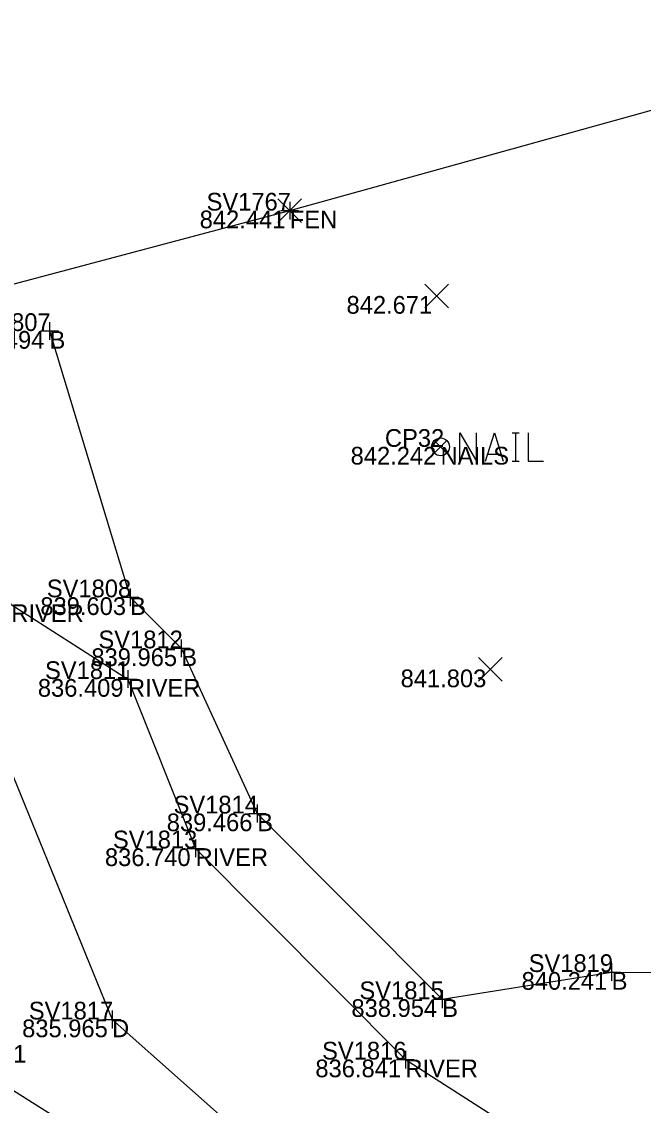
# Model space of a CAD drawing. Extents: x 2125299 to 2129212, y 713100 to 714300.
# Drawn here: x 2127768.7 to 2127803.8, y 713609 to 713670.1 of the extents above; entities that cross this region are included whole.
import ezdxf

# ---------------------------------------------------------------- set-up
doc = ezdxf.new("R2010")
doc.units = 0
for name, color, linetype in [('DR_X_Ditch', 7, 'Continuous'), ('HY_X_Water_Edge', 7, 'Continuous'), ('RD_X_Fence', 7, 'Continuous'), ('RW_P_Esmt_TMP', 7, 'Continuous'), ('RW_X_Esmt_CH', 7, 'Continuous'), ('RW_X_Fee_WL', 7, 'Continuous'), ('SV_X_Break_Lines', 7, 'Continuous'), ('SV_X_Mon_Cells_Found', 7, 'Continuous'), ('SV_X_Text_Elevation', 7, 'Continuous'), ('SV_X_Text_Name', 7, 'Continuous')]:
    doc.layers.add(name, color=color, linetype=linetype)

msp = doc.modelspace()

# ---------------------------------------------------------------- linework, layer by layer
at = {"layer": 'DR_X_Ditch'}
msp.add_lwpolyline([(2127754.532, 713650.693), (2127755.508, 713649.81), (2127761.022, 713641.797), (2127767.377, 713629.627), (2127773.825, 713613.836), (2127787.097, 713602.059), (2127796.409, 713596.425), (2127812.41, 713592.759), (2127822.136, 713591.387), (2127830.865, 713593.325), (2127835.513, 713593.154), (2127840.963, 713588.862), (2127844.441, 713576.862)], dxfattribs=at)
at = {"layer": 'HY_X_Water_Edge'}
for points in [[(2127760.756, 713650.39), (2127768.145, 713637.253), (2127774.726, 713633.041), (2127778.539, 713623.49), (2127790.379, 713611.577), (2127799.446, 713605.767), (2127811.759, 713595.2), (2127821.632, 713592.889), (2127831.559, 713597.952), (2127834.894, 713597.211), (2127837.24, 713606.78), (2127846.533, 713615.952), (2127858.456, 713615.157), (2127864.185, 713615.01), (2127868.763, 713619.475), (2127877.26, 713624.249)], [(2127759.038, 713637.436), (2127761.132, 713628.448), (2127763.153, 713621.237), (2127764.162, 713612.401), (2127775.864, 713605.035), (2127792.881, 713593.368), (2127809.847, 713589.645), (2127822.201, 713590.682), (2127831.261, 713591.73)]]:
    msp.add_lwpolyline(points, dxfattribs=at)
at = {"layer": 'RD_X_Fence'}
msp.add_lwpolyline([(2127758.111, 713652.62), (2127783.853, 713659.466), (2127880.444, 713686.281), (2127925.778, 713698.517)], dxfattribs=at)
at = {"layer": 'SV_X_Break_Lines'}
msp.add_lwpolyline([(2127770.299, 713652.673), (2127774.846, 713637.652), (2127777.731, 713634.773), (2127782.017, 713625.457), (2127792.452, 713614.981), (2127802.011, 713616.513), (2127817.349, 713616.435)], dxfattribs=at)
at = {"layer": 'SV_X_Mon_Cells_Found'}
for p, q in [((2127783.853, 713659.966), (2127783.853, 713658.966)), ((2127783.353, 713659.466), (2127784.353, 713659.466)), ((2127783.853, 713659.466), (2127783.853, 713659.466)), ((2127770.299, 713653.173), (2127770.299, 713652.173)), ((2127769.799, 713652.673), (2127770.799, 713652.673)), ((2127770.299, 713652.673), (2127770.299, 713652.673)), ((2127774.846, 713638.152), (2127774.846, 713637.152)), ((2127774.346, 713637.652), (2127775.346, 713637.652)), ((2127774.846, 713637.652), (2127774.846, 713637.652)), ((2127777.731, 713635.273), (2127777.731, 713634.273)), ((2127777.231, 713634.773), (2127778.231, 713634.773)), ((2127777.731, 713634.773), (2127777.731, 713634.773)), ((2127774.726, 713633.541), (2127774.726, 713632.541)), ((2127774.226, 713633.041), (2127775.226, 713633.041)), ((2127774.726, 713633.041), (2127774.726, 713633.041)), ((2127782.017, 713625.957), (2127782.017, 713624.957)), ((2127781.517, 713625.457), (2127782.517, 713625.457)), ((2127782.017, 713625.457), (2127782.017, 713625.457)), ((2127778.039, 713623.49), (2127779.039, 713623.49)), ((2127778.539, 713623.99), (2127778.539, 713622.99)), ((2127778.539, 713623.49), (2127778.539, 713623.49)), ((2127802.011, 713617.013), (2127802.011, 713616.013)), ((2127801.511, 713616.513), (2127802.511, 713616.513)), ((2127802.011, 713616.513), (2127802.011, 713616.513)), ((2127791.952, 713614.981), (2127792.952, 713614.981)), ((2127792.452, 713615.481), (2127792.452, 713614.481)), ((2127792.452, 713614.981), (2127792.452, 713614.981)), ((2127773.825, 713614.336), (2127773.825, 713613.336)), ((2127773.325, 713613.836), (2127774.325, 713613.836)), ((2127773.825, 713613.836), (2127773.825, 713613.836)), ((2127790.379, 713612.077), (2127790.379, 713611.077)), ((2127789.879, 713611.577), (2127790.879, 713611.577)), ((2127790.379, 713611.577), (2127790.379, 713611.577))]:
    msp.add_line(p, q, dxfattribs=at)
at = {"layer": 'SV_X_Text_Elevation'}
for p, q in [((2127783.186, 713658.798), (2127784.52, 713660.133)), ((2127783.186, 713660.133), (2127784.52, 713658.798)), ((2127791.468, 713653.979), (2127792.802, 713655.314)), ((2127791.468, 713655.314), (2127792.802, 713653.979)), ((2127794.503, 713632.911), (2127795.837, 713634.246)), ((2127794.503, 713634.246), (2127795.837, 713632.911))]:
    msp.add_line(p, q, dxfattribs=at)
at = {"layer": 'SV_X_Text_Name'}
for p, q in [((2127792.005, 713646.492), (2127792.713, 713645.785)), ((2127792.005, 713645.785), (2127792.713, 713646.492))]:
    msp.add_line(p, q, dxfattribs=at)
for points in [[(2127793.449, 713645.329), (2127793.449, 713646.929), (2127794.393, 713645.329), (2127794.393, 713646.929)], [(2127794.897, 713645.329), (2127795.401, 713646.929), (2127795.892, 713645.329)], [(2127796.396, 713646.929), (2127796.799, 713646.929)], [(2127796.598, 713645.329), (2127796.598, 713646.929)], [(2127797.303, 713646.929), (2127797.303, 713645.329), (2127798.173, 713645.329)], [(2127795.766, 713645.706), (2127795.023, 713645.706)], [(2127796.396, 713645.329), (2127796.799, 713645.329)]]:
    msp.add_lwpolyline(points, dxfattribs=at)
msp.add_circle((2127792.359, 713646.138), 0.5, dxfattribs=at)

# ---------------------------------------------------------------- texts
at = {"layer": 'RW_P_Esmt_TMP'}
for s, p in [('FEN', (2127783.853, 713658.466)), ('B', (2127770.299, 713651.673)), ('NAILS', (2127792.359, 713645.138)), ('B', (2127774.846, 713636.652)), ('RIVER', (2127768.145, 713636.253)), ('B', (2127777.731, 713633.773)), ('RIVER', (2127774.726, 713632.042)), ('B', (2127782.017, 713624.457)), ('RIVER', (2127778.539, 713622.49)), ('B', (2127802.011, 713615.513)), ('B', (2127792.452, 713613.981)), ('D', (2127773.825, 713612.836)), ('RIVER1', (2127764.162, 713611.401)), ('RIVER', (2127790.379, 713610.577))]:
    msp.add_text(s, height=1, dxfattribs=at).set_placement(p)
at = {"layer": 'RW_X_Esmt_CH'}
for s, p in [('SV1767', (2127779.159, 713659.466)), ('SV1807', (2127765.605, 713652.673)), ('CP32', (2127789.22, 713646.138)), ('SV1808', (2127770.147, 713637.652)), ('SV1812', (2127773.06, 713634.773)), ('SV1811', (2127770.046, 713633.041)), ('SV1814', (2127777.297, 713625.457)), ('SV1813', (2127773.877, 713623.49)), ('SV1819', (2127797.329, 713616.513)), ('SV1815', (2127787.783, 713614.981)), ('SV1817', (2127769.131, 713613.836)), ('SV1816', (2127785.677, 713611.577))]:
    msp.add_text(s, height=1, dxfattribs=at).set_placement(p)
at = {"layer": 'RW_X_Fee_WL'}
for s, p in [('842.441', (2127778.771, 713658.466)), ('842.441', (2127778.771, 713658.466)), ('842.671', (2127787.053, 713653.647)), ('840.494', (2127765.177, 713651.673)), ('842.242', (2127787.286, 713645.138)), ('839.603', (2127769.782, 713636.652)), ('839.965', (2127772.661, 713633.773)), ('841.803', (2127790.106, 713632.578)), ('836.409', (2127769.642, 713632.042)), ('839.466', (2127776.913, 713624.457)), ('836.740', (2127773.425, 713622.49)), ('840.241', (2127796.929, 713615.513)), ('838.954', (2127787.33, 713613.981)), ('835.965', (2127768.755, 713612.836)), ('836.841', (2127785.297, 713610.577))]:
    msp.add_text(s, height=1, dxfattribs=at).set_placement(p)

doc.saveas('drawing.dxf')
